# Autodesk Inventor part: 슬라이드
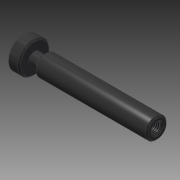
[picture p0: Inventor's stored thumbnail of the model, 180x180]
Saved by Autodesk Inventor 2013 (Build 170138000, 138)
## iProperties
Created: 2015-12
Part Number: 슬라이드
Document SubType Name: Modeling
Designer: mdu
Density: 8.08 g/cm^3
Material: 스테인리스강
Mass: 104.213 g
Surface Area: 46.388 cm^2
Volume: 12.8976 cm^3
Author: mdu
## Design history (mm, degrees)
sketch "스케치1"
  geometry: L1 (-40, 0)-(40, 0); L2 (-40, 0)-(-40, 11); L3 (-40, 11)-(-32, 11); L4 (-32, 11)-(-32, 4); L5 (-32, 4)-(-27, 4); L6 (-27, 4)-(-24, 7); L7 (-24, 7)-(40, 7); L8 (40, 7)-(40, 0); 2 further points
  constraints: 16 end point, 4 parallel, 2 perpendicular, 1 coincident, 1 horizontal, 1 midpoint
  dimensions: "d0" = 80 distance of L1.start L1.end; "d1" = 22 diameter of L3 L1; "d2" = 14 diameter of L7 L1; "d3" = 8 diameter of L5 L1; "d4" = 8 distance of L2.end L3.end; "d5" = 5 distance of L4.end L5.end; "d6" = 135 deg angle of L6 L5
revolve "회전1" sketch "스케치1" stored, may be unused: angle "d7" = 90 deg
chamfer "모따기1" distance "d8" = 1; stored, may be unused: second distance "d9" = 2, angle "d10" = 45 deg
hole "구멍1" diameter "d13" = 6.647; stored, may be unused: countersink angle "d17" = 90 deg, drill point angle "d19" = 118 deg; dims "d11" = 10, "d12" = 10, "d14" = 9, "d15" = 4, "d16" = 2, "d18" = 12
chamfer "모따기2" distance "d20" = 1; stored, may be unused: second distance "d21" = 2, angle "d22" = 45 deg
node "솔리드1"
